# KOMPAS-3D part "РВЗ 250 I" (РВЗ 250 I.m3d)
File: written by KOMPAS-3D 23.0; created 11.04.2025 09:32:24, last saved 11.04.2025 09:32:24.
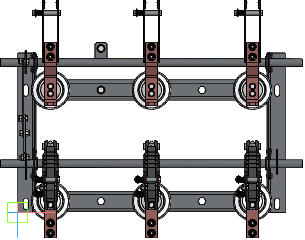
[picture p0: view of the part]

Document properties: Автор: pc; Полное имя файла: C:\Users\pc\Desktop\работа\РВЗ\3D макеты\РВЗ 250 I.m3d

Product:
- Body: Тело 1
    Масса: 0.01131
- Body: Тело 2
    Масса: 0.01131
- Body: Тело 3
    Масса: 1.849184
- Body: Тело 4
    Масса: 1.849184
- Part/product: РВЗ 250 I
    Масса: 3.720987

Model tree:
1. Операция без истории:1
2. Операция без истории:2
3. Операция без истории:3
4. Операция без истории:4
5. Поверхность без истории:1
6. Поверхность без истории:2
7. Поверхность без истории:3
8. Поверхность без истории:4
9. Поверхность без истории:5
10. Поверхность без истории:6
11. Поверхность без истории:7
12. Поверхность без истории:8
13. Поверхность без истории:9
14. Поверхность без истории:10
15. Поверхность без истории:11
16. Поверхность без истории:12
17. Поверхность без истории:13
18. Поверхность без истории:14
19. Поверхность без истории:15
20. Поверхность без истории:16
21. Поверхность без истории:17
22. Поверхность без истории:18
23. Поверхность без истории:19
24. Поверхность без истории:20
25. Поверхность без истории:21
26. Поверхность без истории:22
27. Поверхность без истории:23
28. Поверхность без истории:24
29. Поверхность без истории:25
30. Поверхность без истории:26
31. Поверхность без истории:27
32. Поверхность без истории:28
33. Поверхность без истории:29
34. Поверхность без истории:30
35. Поверхность без истории:31
36. Поверхность без истории:32
37. Поверхность без истории:33
38. Поверхность без истории:34
39. Поверхность без истории:35
40. Поверхность без истории:36
41. Поверхность без истории:37
42. Поверхность без истории:38
43. Поверхность без истории:39
44. Поверхность без истории:40
45. Поверхность без истории:41
46. Поверхность без истории:42
47. Поверхность без истории:43
48. Поверхность без истории:44
49. Поверхность без истории:45
50. Поверхность без истории:46
51. Поверхность без истории:47
52. Поверхность без истории:48
53. Поверхность без истории:49
54. Поверхность без истории:50
55. Поверхность без истории:51
56. Поверхность без истории:52
57. Поверхность без истории:53
58. Поверхность без истории:54
59. Поверхность без истории:55
60. Поверхность без истории:56
61. Поверхность без истории:57
62. Поверхность без истории:58
63. Поверхность без истории:59
64. Поверхность без истории:60
65. Поверхность без истории:61
66. Поверхность без истории:62
67. Поверхность без истории:63
68. Поверхность без истории:64
69. Поверхность без истории:65
70. Поверхность без истории:66
71. Поверхность без истории:67
72. Поверхность без истории:68
73. Поверхность без истории:69
74. Поверхность без истории:70
75. Поверхность без истории:71
76. Поверхность без истории:72
77. Поверхность без истории:73
78. Поверхность без истории:74
79. Поверхность без истории:75
80. Поверхность без истории:76
81. Поверхность без истории:77
82. Поверхность без истории:78
83. Поверхность без истории:79
84. Поверхность без истории:80
85. Поверхность без истории:81
86. Поверхность без истории:82
87. Поверхность без истории:83
88. Поверхность без истории:84
89. Поверхность без истории:85
90. Поверхность без истории:86
91. Поверхность без истории:87
92. Поверхность без истории:88
93. Поверхность без истории:89
94. Поверхность без истории:90
95. Поверхность без истории:91
96. Поверхность без истории:92
97. Поверхность без истории:93
98. Поверхность без истории:94
99. Поверхность без истории:95
100. Поверхность без истории:96
101. Поверхность без истории:97
102. Поверхность без истории:98
103. Поверхность без истории:99
104. Поверхность без истории:100
105. Поверхность без истории:101
106. Поверхность без истории:102
107. Поверхность без истории:103
108. Поверхность без истории:104
109. Поверхность без истории:105
110. Поверхность без истории:106
111. Поверхность без истории:107
112. Поверхность без истории:108
113. Поверхность без истории:109
114. Поверхность без истории:110
115. Поверхность без истории:111
116. Поверхность без истории:112
117. Поверхность без истории:113
118. Поверхность без истории:114
119. Поверхность без истории:115
120. Поверхность без истории:116
121. Поверхность без истории:117
122. Поверхность без истории:118
123. Поверхность без истории:119
124. Поверхность без истории:120
125. Поверхность без истории:121
126. Поверхность без истории:122
127. Поверхность без истории:123
128. Поверхность без истории:124
129. Поверхность без истории:125
130. Поверхность без истории:126
131. Поверхность без истории:127
132. Поверхность без истории:128
133. Поверхность без истории:129
134. Поверхность без истории:130
135. Поверхность без истории:131
136. Поверхность без истории:132
137. Поверхность без истории:133
138. Поверхность без истории:134
139. Поверхность без истории:135
140. Поверхность без истории:136
141. Поверхность без истории:137
142. Поверхность без истории:138
143. Поверхность без истории:139
144. Поверхность без истории:140
145. Поверхность без истории:141
146. Поверхность без истории:142
147. Поверхность без истории:143
148. Поверхность без истории:144
149. Поверхность без истории:145
150. Поверхность без истории:146
151. Поверхность без истории:147
152. Поверхность без истории:148
153. Поверхность без истории:149
154. Поверхность без истории:150
155. Поверхность без истории:151
156. Поверхность без истории:152
157. Поверхность без истории:153
158. Поверхность без истории:154
159. Поверхность без истории:155
160. Поверхность без истории:156
161. Поверхность без истории:157
162. Поверхность без истории:158
163. Поверхность без истории:159
164. Поверхность без истории:160
165. Поверхность без истории:161
166. Поверхность без истории:162
167. Поверхность без истории:163
168. Поверхность без истории:164
169. Поверхность без истории:165
170. Поверхность без истории:166
171. Поверхность без истории:167
172. Поверхность без истории:168
173. Поверхность без истории:169
174. Поверхность без истории:170
175. Поверхность без истории:171
176. Поверхность без истории:172
177. Поверхность без истории:173
178. Поверхность без истории:174
179. Поверхность без истории:175
180. Поверхность без истории:176
181. Поверхность без истории:177
182. Поверхность без истории:178
183. Поверхность без истории:179
184. Поверхность без истории:180
185. Поверхность без истории:181
186. Поверхность без истории:182
187. Поверхность без истории:183
188. Поверхность без истории:184
189. Поверхность без истории:185
190. Поверхность без истории:186
191. Поверхность без истории:187
192. Поверхность без истории:188
193. Поверхность без истории:189
194. Поверхность без истории:190
195. Поверхность без истории:191
196. Поверхность без истории:192
197. Поверхность без истории:193
198. Поверхность без истории:194
199. Поверхность без истории:195
200. Поверхность без истории:196
201. Поверхность без истории:197
202. Поверхность без истории:198
203. Поверхность без истории:199
204. Поверхность без истории:200
205. Поверхность без истории:201
206. Поверхность без истории:202
207. Поверхность без истории:203
208. Поверхность без истории:204
209. Поверхность без истории:205
210. Поверхность без истории:206
211. Поверхность без истории:207
212. Поверхность без истории:208
213. Поверхность без истории:209
214. Поверхность без истории:210
215. Поверхность без истории:211
216. Поверхность без истории:212
217. Поверхность без истории:213
218. Поверхность без истории:214
219. Поверхность без истории:215
220. Поверхность без истории:216
221. Поверхность без истории:217
222. Поверхность без истории:218
223. Поверхность без истории:219
224. Поверхность без истории:220
225. Поверхность без истории:221
226. Поверхность без истории:222
227. Поверхность без истории:223
228. Поверхность без истории:224
229. Поверхность без истории:225
230. Поверхность без истории:226
231. Поверхность без истории:227
232. Поверхность без истории:228
233. Поверхность без истории:229
234. Поверхность без истории:230
235. Поверхность без истории:231
236. Поверхность без истории:232
237. Поверхность без истории:233
238. Поверхность без истории:234
239. Поверхность без истории:235
240. Поверхность без истории:236
241. Поверхность без истории:237
242. Поверхность без истории:238
243. Поверхность без истории:239
244. Поверхность без истории:240
245. Поверхность без истории:241
246. Поверхность без истории:242
247. Поверхность без истории:243
248. Поверхность без истории:244
249. Поверхность без истории:245
250. Поверхность без истории:246
251. Поверхность без истории:247
252. Поверхность без истории:248
253. Поверхность без истории:249
254. Поверхность без истории:250
255. Поверхность без истории:251
256. Поверхность без истории:252
257. Поверхность без истории:253
258. Поверхность без истории:254
259. Поверхность без истории:255
260. Поверхность без истории:256
261. Поверхность без истории:257
262. Поверхность без истории:258
263. Поверхность без истории:259
264. Поверхность без истории:260
265. Поверхность без истории:261
266. Поверхность без истории:262
267. Поверхность без истории:263
268. Поверхность без истории:264
269. Поверхность без истории:265
270. Поверхность без истории:266
271. Поверхность без истории:267
272. Поверхность без истории:268
273. Поверхность без истории:269
274. Поверхность без истории:270
275. Поверхность без истории:271
276. Поверхность без истории:272
277. Поверхность без истории:273
278. Поверхность без истории:274
279. Поверхность без истории:275
280. Поверхность без истории:276
281. Поверхность без истории:277
282. Поверхность без истории:278
283. Поверхность без истории:279
284. Поверхность без истории:280
285. Поверхность без истории:281
286. Поверхность без истории:282
287. Поверхность без истории:283
288. Поверхность без истории:284
289. Поверхность без истории:285
290. Поверхность без истории:286
291. Поверхность без истории:287
292. Поверхность без истории:288
293. Поверхность без истории:289
294. Поверхность без истории:290
295. Поверхность без истории:291
296. Поверхность без истории:292
297. Поверхность без истории:293
298. Поверхность без истории:294
299. Поверхность без истории:295
300. Поверхность без истории:296
301. Поверхность без истории:297
302. Поверхность без истории:298
303. Поверхность без истории:299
